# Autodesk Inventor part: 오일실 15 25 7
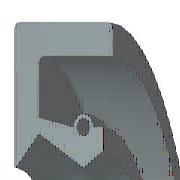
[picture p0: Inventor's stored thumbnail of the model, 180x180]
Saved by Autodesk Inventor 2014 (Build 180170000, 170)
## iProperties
Created: 2012-02
Part Number: 오일실 15 25 7
Material: 고무
Description: 오일-실
Document SubType Name: Modeling
Standard: KS B 2804
Designer: mduedu
Standards Organization: KS
Language: ko-KR
Size Designation: D - 15 25 7
Categories: <MemberInstance><Categories><Category DisplayName="샤프트 부품" InternalName="7f7aeb1f-a693-4053-b835-cee3144e0d98" Mnemonic="SHFT"><Category DisplayName="실링" Intern
Density: 0.93 g/cm^3
Appearance: Rubber - Black - Version 1.1
IsCustomPart: 1
Author: mduedu
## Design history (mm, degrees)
revolve "본체" stored, may be unused: angle "d17" = 90 deg
revolve "스프링1" stored, may be unused: angle "d18" = 90 deg
body "Solid1"
sketch "스케치1"
  geometry: L1 (0, 12.5)-(7, 12.5); L2 (7, 10.75)-(1.75, 10.75); L3 (1.75, 9.25)-(4.9, 7.5); L4 (4.9, 7.5)-(0, 7.5); L5 (0, 0)-(9.586, 0) reference; L6 (4.9, 7.5)-(6.3, 8.375); L7 (0, 18)-(0, -3) reference; L8 (-1.941, 0)-(11.507, 0) reference; L9 (4.2, 9.6)-(1.75, 10.09); L10 (1.75, 10.09)-(1.75, 10.75); L11 (0, 12.5)-(0, 7.588); L12 (4.9, 7.5)-(0, 7.5); L13 (1.75, 9.25)-(0.152, 7.528); L14 (7, 12.5)-(7, 10.75); L15 (5.6, 9.6)-(6.3, 9.6); L16 (6.3, 9.6)-(6.3, 8.375); C1 r 0.455 at (4.9, 9.6); A1 r 0.7 centre (4.9, 9.6) between (5.6, 9.6) and (4.2, 9.6); A2 r 0.088 centre (0.088, 7.588) between (0, 7.588) and (0.152, 7.528); 1 further point
  constraints: 28 end point, 5 horizontal alignment, 5 point on line, 4 point on circle, 4 vertical alignment, 3 centre point, 3 tangent, 2 collinear, 2 horizontal, 2 perpendicular, 1 coincident, 1 parallel
  dimensions: "d0" = 25 diameter of L1 L5 (= SD2); "d1" = 1.75 distance of L1.end L2.start (= SD); "d2" = 0.91 diameter of C1 (= SPDI); "d3" = 1.4 diameter of A1 (= SPDA); "d4" = 15 diameter of L3.end L5 (= NND); "d5" = 18.5 diameter of L3.start L5 (= TKDM); "d7" = 20.18 diameter of L9.end L5 (= TKDM + 0.24 x SWDT); "d8" = 1.75 distance between parallel lines of L11 L10 (= SD); "d9" = 4.9 distance from line of L11 C1.centre (= SPDST); "d10" = 19.2 diameter of C1.centre L5 (= HLDM); "d11" = 0.0875 radius of A2 (= 0.25 x LAB); "d12" = 6.3 distance between parallel lines of L11 L16 (= SDI); "d13" = 16.75 diameter of L6.end L5 (= ABDM); "d14" = 7 distance from line of L11 L1.end (= SWDT)
fillet "모깎기1" dims "d6" = 0.3 (= RR)
other parameters: "SD2" = 25 [user parameter; used in 1 equation term], "SWDT" = 7 [user parameter; used in 2 equation terms], "RR" = 0.3 [user parameter; used in 1 equation term], "SD" = 1.75 [user parameter; used in 2 equation terms], "NND" = 15 [user parameter; used in 1 equation term], "SPDA" = 1.4 [user parameter; used in 1 equation term], "SPDI" = 0.91 [user parameter; used in 1 equation term], "TKDM" = 18.5 [user parameter; used in 2 equation terms], "HLDM" = 19.2 [user parameter; used in 1 equation term], "ABDM" = 16.75 [user parameter; used in 1 equation term], "SDI" = 6.3 [user parameter; used in 1 equation term], "SPDST" = 4.9 [user parameter; used in 1 equation term], "LAB" = 0.35 [user parameter; used in 1 equation term], "d15" = 0, "d16" = 0, "d19" = 0
